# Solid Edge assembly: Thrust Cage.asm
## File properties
Last saved by: Dan
Revision: 53
Project Name: Piston Pump P52
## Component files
Cage 44-85-3,5.par
Cyl Roller 5-8.par
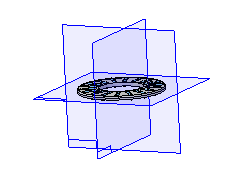
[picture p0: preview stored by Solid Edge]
